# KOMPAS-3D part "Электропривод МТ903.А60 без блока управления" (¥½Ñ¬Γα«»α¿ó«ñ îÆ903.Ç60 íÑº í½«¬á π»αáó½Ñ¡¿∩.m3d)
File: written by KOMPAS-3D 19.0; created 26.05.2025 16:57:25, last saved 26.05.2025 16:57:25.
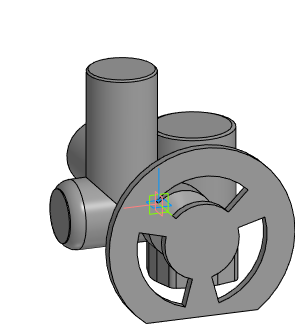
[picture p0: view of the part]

Document properties: Полное имя файла: E:\Dendor Работа Сачек\3D для проекитирвщиков\3.4 Электропривод МТ903.А\stp_Тип МТ903.А без блока управления\Электропривод МТ903.А60 без блока управления.m3d

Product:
- Part/product: Электропривод МТ903.А60 без блока управления

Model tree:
1. Операция без истории:1  (labels: Электропривод МТ903.А60 без блока управления)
